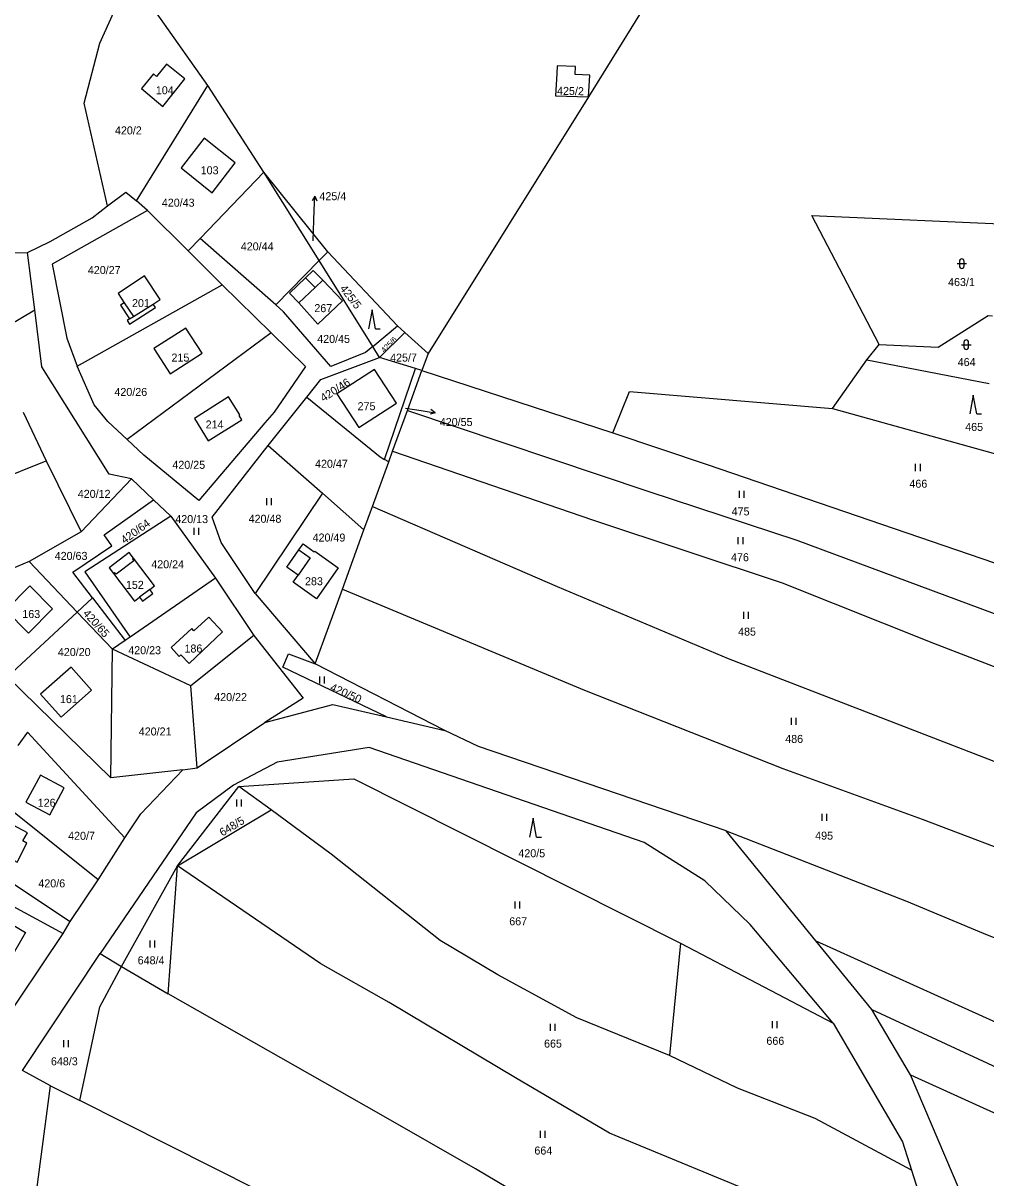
# Model space of a CAD drawing. Extents: x -7483133 to -743907, y -11317770 to -1129777.
# Drawn here: x -748843.6 to -748639.1, y -1130642.1 to -1130396.9 of the extents above; entities that cross this region are included whole.
import ezdxf

# ---------------------------------------------------------------- set-up
doc = ezdxf.new("R2010")
doc.units = 0
for name, color, linetype in [('Hranice parcel', 7, 'Continuous'), ('Parcelní čísla', 7, 'Continuous'), ('Pop  PČ popisy', 7, 'Continuous'), ('Vnitřní kresba', 7, 'Continuous'), ('Značky kultur', 7, 'Continuous')]:
    doc.layers.add(name, color=color, linetype=linetype)

msp = doc.modelspace()

# ---------------------------------------------------------------- linework, layer by layer
at = {"layer": 'Hranice parcel'}
for p, q in [((-748819.51, -1130434.58), (-748804.37, -1130410.14)), ((-748792.44, -1130428.53), (-748804.37, -1130410.14)), ((-748805.98, -1130442.59), (-748792.44, -1130428.53)), ((-748778.89, -1130445.44), (-748792.44, -1130428.53)), ((-748780.72, -1130447.3), (-748792.44, -1130428.53)), ((-748817.21, -1130436.65), (-748819.51, -1130434.58)), ((-748808.51, -1130445.24), (-748817.21, -1130436.65)), ((-748805.98, -1130442.59), (-748808.51, -1130445.24)), ((-748789.95, -1130456.7), (-748805.98, -1130442.59)), ((-748848.41, -1130445.73), (-748842.67, -1130445.58)), ((-748841.12, -1130457.78), (-748842.67, -1130445.58)), ((-748801.29, -1130452.44), (-748808.51, -1130445.24)), ((-748780.72, -1130447.3), (-748778.89, -1130445.44)), ((-748764.11, -1130461.14), (-748778.89, -1130445.44)), ((-748789.95, -1130456.7), (-748780.72, -1130447.3)), ((-748769.34, -1130465.53), (-748780.72, -1130447.3)), ((-748832.08, -1130469.75), (-748801.29, -1130452.44)), ((-748801.29, -1130452.44), (-748790.91, -1130462.62)), ((-748846.67, -1130461.06), (-748841.12, -1130457.78)), ((-748839.58, -1130469.86), (-748841.12, -1130457.78)), ((-748788.31, -1130458.17), (-748789.95, -1130456.7)), ((-748790.91, -1130462.62), (-748821.52, -1130485.28)), ((-748790.91, -1130462.62), (-748783.62, -1130469.82)), ((-748769.34, -1130465.53), (-748764.11, -1130461.14)), ((-748767.88, -1130467.87), (-748762.56, -1130462.59)), ((-748762.56, -1130462.59), (-748764.11, -1130461.14)), ((-748757.6, -1130467.05), (-748762.56, -1130462.59)), ((-748664.43, -1130468.41), (-748661.8, -1130465.15)), ((-748769.34, -1130465.53), (-748770.9, -1130466.83)), ((-748767.88, -1130467.87), (-748769.34, -1130465.53)), ((-748760.27, -1130470.2), (-748767.88, -1130467.87)), ((-748757.6, -1130467.05), (-748758.89, -1130470.62)), ((-748766.84, -1130489.51), (-748760.27, -1130470.2)), ((-748758.89, -1130470.62), (-748760.27, -1130470.2)), ((-748671.7, -1130478.68), (-748664.43, -1130468.41)), ((-748664.43, -1130468.41), (-748638.43, -1130473.4)), ((-748761.98, -1130479.13), (-748758.89, -1130470.62)), ((-748758.89, -1130470.62), (-748718.34, -1130483.88)), ((-748791.56, -1130486.57), (-748783.35, -1130476.32)), ((-748843.6, -1130479.46), (-748838.72, -1130489.81)), ((-748765.12, -1130487.78), (-748761.98, -1130479.13)), ((-748797.15, -1130481.13), (-748797.74, -1130480.18)), ((-748803.45, -1130501.81), (-748791.56, -1130486.57)), ((-748791.56, -1130486.57), (-748779.98, -1130496.71)), ((-748838.72, -1130489.81), (-748831.25, -1130504.91)), ((-748765.94, -1130490.05), (-748766.84, -1130489.51)), ((-748765.94, -1130490.05), (-748765.12, -1130487.78)), ((-748769.41, -1130499.53), (-748765.94, -1130490.05)), ((-748831.25, -1130504.91), (-748820.54, -1130493.62)), ((-748820.54, -1130493.62), (-748815.91, -1130498.09)), ((-748779.98, -1130496.71), (-748794.31, -1130518)), ((-748771.22, -1130504.47), (-748779.98, -1130496.71)), ((-748815.91, -1130498.09), (-748812.25, -1130501.61)), ((-748771.22, -1130504.47), (-748769.41, -1130499.53)), ((-748812.25, -1130501.61), (-748802.76, -1130514.74)), ((-748775.79, -1130517.06), (-748771.22, -1130504.47)), ((-748831.25, -1130504.91), (-748842.3, -1130511.21)), ((-748842.3, -1130511.21), (-748863.15, -1130519.89)), ((-748832.1, -1130521.99), (-748842.3, -1130511.21)), ((-748802.76, -1130514.74), (-748820.87, -1130527.26)), ((-748802.76, -1130514.74), (-748794.57, -1130526.92)), ((-748832.1, -1130521.99), (-748828.83, -1130518.95)), ((-748828.83, -1130518.95), (-748821.95, -1130528)), ((-748794.31, -1130518), (-748781.55, -1130532.95)), ((-748781.55, -1130532.95), (-748775.79, -1130517.06)), ((-748846.93, -1130535.69), (-748832.1, -1130521.99)), ((-748824.58, -1130529.82), (-748832.1, -1130521.99)), ((-748821.95, -1130528), (-748824.58, -1130529.82)), ((-748820.87, -1130527.26), (-748821.95, -1130528)), ((-748794.57, -1130526.92), (-748807.97, -1130537.59)), ((-748824.94, -1130557.15), (-748824.58, -1130529.82)), ((-748807.97, -1130537.59), (-748824.58, -1130529.82)), ((-748754, -1130547.08), (-748781.55, -1130532.95)), ((-748824.94, -1130557.15), (-748846.93, -1130535.69)), ((-748806.63, -1130555.06), (-748807.97, -1130537.59)), ((-748806.63, -1130555.06), (-748792.29, -1130545.43)), ((-748766.4, -1130544.2), (-748754, -1130547.08)), ((-748842.68, -1130547.42), (-748844.69, -1130550.29)), ((-748822.02, -1130569.92), (-748842.68, -1130547.42)), ((-748809.68, -1130555.47), (-748824.94, -1130557.15)), ((-748809.68, -1130555.47), (-748806.63, -1130555.06)), ((-748827.67, -1130578.81), (-748852.67, -1130558.78)), ((-748810.8, -1130575.84), (-748797.81, -1130558.97)), ((-748790.94, -1130563.97), (-748797.81, -1130558.97)), ((-748810.8, -1130575.84), (-748790.94, -1130563.97)), ((-748675.21, -1130591.78), (-748694.25, -1130568.39)), ((-748860.1, -1130570.08), (-748833.58, -1130587.64)), ((-748827.67, -1130578.81), (-748822.02, -1130569.92)), ((-748863.53, -1130574.84), (-748835.11, -1130590.22)), ((-748822.71, -1130597.23), (-748810.8, -1130575.84)), ((-748812.78, -1130603.03), (-748810.8, -1130575.84)), ((-748833.58, -1130587.64), (-748827.67, -1130578.81)), ((-748835.11, -1130590.22), (-748833.58, -1130587.64)), ((-748851.72, -1130614.96), (-748835.11, -1130590.22)), ((-748704.01, -1130592.27), (-748706.33, -1130616.12)), ((-748704.01, -1130592.27), (-748671.54, -1130609.27)), ((-748663.32, -1130606.39), (-748675.21, -1130591.78)), ((-748843.69, -1130619.33), (-748827.25, -1130594.48)), ((-748827.25, -1130594.48), (-748822.71, -1130597.23)), ((-748822.71, -1130597.23), (-748812.78, -1130603.03)), ((-748655.15, -1130620.24), (-748663.32, -1130606.39)), ((-748837.76, -1130622.58), (-748843.69, -1130619.33)), ((-748655.15, -1130620.24), (-748603.37, -1130643.75)), ((-748644.81, -1130644.52), (-748655.15, -1130620.24)), ((-748841.05, -1130647.3), (-748837.76, -1130622.58)), ((-748837.76, -1130622.58), (-748831.53, -1130625.71)), ((-748654.93, -1130640.47), (-748646.91, -1130665.97))]:
    msp.add_line(p, q, dxfattribs=at)
for points in [[(-748668.63, -1130323.88), (-748723.49, -1130412.55), (-748757.6, -1130467.05)], [(-748825.64, -1130435.7), (-748830.6, -1130413.85), (-748827.29, -1130401.09), (-748824.29, -1130394.55), (-748817.71, -1130391.16)], [(-748804.37, -1130410.14), (-748815.28, -1130394.69), (-748817.71, -1130391.16)], [(-748815.24, -1130408.18), (-748815.91, -1130407.67), (-748818.48, -1130410.72), (-748813.94, -1130414.55), (-748809.28, -1130408.69), (-748813.12, -1130405.56), (-748815.24, -1130408.18)], [(-748730.17, -1130405.92), (-748730.26, -1130407.59), (-748730.51, -1130412.32), (-748723.49, -1130412.55), (-748723.25, -1130407.92), (-748726.36, -1130407.78), (-748726.31, -1130406.11), (-748730.17, -1130405.92)], [(-748798.53, -1130426.57), (-748805.14, -1130421.28), (-748810.06, -1130427.6)], [(-748810.06, -1130427.6), (-748803.47, -1130432.9), (-748798.53, -1130426.57)], [(-748825.64, -1130435.7), (-748821.76, -1130432.75), (-748819.51, -1130434.58)], [(-748842.67, -1130445.58), (-748837.83, -1130443.26), (-748828.93, -1130438.2), (-748825.64, -1130435.7)], [(-748817.21, -1130436.65), (-748837.42, -1130448.09), (-748834.32, -1130463.8), (-748832.08, -1130469.75)], [(-748661.8, -1130465.15), (-748676.09, -1130437.74), (-748631.31, -1130439.73)], [(-748822.89, -1130456.78), (-748820.97, -1130459.7), (-748821.47, -1130460.02), (-748820.98, -1130460.78), (-748815.5, -1130457.27), (-748815.97, -1130456.53), (-748814.52, -1130455.58), (-748817.78, -1130450.55), (-748823.43, -1130454.26), (-748822.1, -1130456.26), (-748822.89, -1130456.78)], [(-748781, -1130460.83), (-748775.78, -1130455.82), (-748779.97, -1130451.47), (-748781.98, -1130449.37), (-748783.6, -1130450.93), (-748787.01, -1130454.2), (-748785.04, -1130456.25), (-748781, -1130460.83)], [(-748770.9, -1130466.83), (-748778.22, -1130469.78), (-748788.31, -1130458.17)], [(-748661.8, -1130465.15), (-748649.27, -1130465.67), (-748638.63, -1130458.96), (-748637.75, -1130459.01)], [(-748805.57, -1130466.96), (-748809.03, -1130461.64), (-748815.82, -1130465.97), (-748812.39, -1130471.35), (-748805.57, -1130466.96)], [(-748783.35, -1130476.32), (-748780.36, -1130472.52), (-748767.88, -1130467.87)], [(-748820.54, -1130493.62), (-748825.34, -1130492.64), (-748839.58, -1130469.86)], [(-748821.52, -1130485.28), (-748825.63, -1130481.5), (-748828.48, -1130477.93), (-748832.08, -1130469.75)], [(-748783.62, -1130469.82), (-748790.29, -1130479.46), (-748792.26, -1130481.76), (-748806.27, -1130498.24)], [(-748772.28, -1130482.78), (-748764.3, -1130477.55), (-748768.99, -1130470.4), (-748776.95, -1130475.63), (-748772.28, -1130482.78)], [(-748718.34, -1130483.88), (-748714.81, -1130475.07), (-748671.7, -1130478.68)], [(-748797.74, -1130480.18), (-748797.55, -1130480.06), (-748799.94, -1130476.26), (-748807.21, -1130480.86), (-748804.28, -1130485.57), (-748797.15, -1130481.13)], [(-748783.35, -1130476.32), (-748767.74, -1130488.96), (-748766.84, -1130489.51)], [(-748761.98, -1130479.13), (-748710.91, -1130496.25), (-748679.26, -1130506.7), (-748621.93, -1130527.97)], [(-748671.7, -1130478.68), (-748633.74, -1130489.24), (-748618.21, -1130483.5)], [(-748718.34, -1130483.88), (-748698.29, -1130490.59), (-748629.43, -1130514.15)], [(-748806.27, -1130498.24), (-748817.98, -1130488.65), (-748821.52, -1130485.28)], [(-748868.14, -1130501.65), (-748849.28, -1130494.06), (-748838.72, -1130489.81)], [(-748765.12, -1130487.78), (-748722.68, -1130502.34), (-748682.4, -1130515.73), (-748650.26, -1130528.57), (-748607.86, -1130544.88)], [(-748828.83, -1130518.95), (-748833.02, -1130513.48), (-748824.76, -1130507.89), (-748826.36, -1130505.51), (-748815.91, -1130498.09)], [(-748769.41, -1130499.53), (-748730.21, -1130516.5), (-748693.83, -1130531.8), (-748627.18, -1130557.56), (-748603.84, -1130566.17), (-748577.63, -1130576.56)], [(-748812.25, -1130501.61), (-748830.46, -1130513.37), (-748820.87, -1130527.26)], [(-748794.31, -1130518), (-748801.5, -1130507.17), (-748803.45, -1130501.81)], [(-748816.7, -1130517.18), (-748815.67, -1130516.4), (-748820.14, -1130510.48), (-748821.04, -1130509.29), (-748825.32, -1130512.52)], [(-748785.03, -1130508.74), (-748784.15, -1130507.49), (-748781.75, -1130509.19), (-748781.63, -1130509.04), (-748776.67, -1130512.52), (-748781.3, -1130519.11), (-748786.27, -1130515.61), (-748785.21, -1130514.11), (-748787.62, -1130512.4), (-748785.03, -1130508.74)], [(-748825.32, -1130512.52), (-748824.39, -1130513.73), (-748819.95, -1130519.63), (-748818.86, -1130518.81), (-748818.22, -1130519.65), (-748816.06, -1130518.02), (-748816.7, -1130517.18)], [(-748837.33, -1130521.27), (-748842.14, -1130516.36), (-748847.28, -1130521.51), (-748842.48, -1130526.4), (-748837.33, -1130521.27)], [(-748775.79, -1130517.06), (-748724.37, -1130538.57), (-748682.28, -1130555.19), (-748652.69, -1130565.92), (-748602.7, -1130584.94), (-748579.32, -1130593.13)], [(-748807.77, -1130525.47), (-748812.13, -1130529.47), (-748810.42, -1130531.37), (-748810.07, -1130531.04), (-748808.34, -1130532.87), (-748801.24, -1130526.14), (-748804.12, -1130523), (-748807.33, -1130525.95), (-748807.77, -1130525.47)], [(-748794.57, -1130526.92), (-748784.09, -1130540.23), (-748792.29, -1130545.43)], [(-748766.4, -1130544.2), (-748788.4, -1130533.64), (-748787.24, -1130530.81), (-748781.55, -1130532.95)], [(-748829.04, -1130538.57), (-748833.41, -1130533.62), (-748839.91, -1130539.35), (-748835.51, -1130544.26), (-748829.04, -1130538.57)], [(-748792.29, -1130545.43), (-748777.8, -1130541.55), (-748766.4, -1130544.2)], [(-748694.25, -1130568.39), (-748746.89, -1130550.49), (-748754, -1130547.08)], [(-748671.54, -1130609.27), (-748689.21, -1130588.28), (-748698.85, -1130579.03), (-748711.73, -1130570.87), (-748770.07, -1130550.7), (-748789.66, -1130553.8), (-748798.91, -1130558.69), (-748806.83, -1130564.57), (-748827.25, -1130594.48)], [(-748822.02, -1130569.92), (-748818.59, -1130564.8), (-748809.68, -1130555.47)], [(-748843.04, -1130562.3), (-748837.93, -1130565), (-748834.89, -1130559.25), (-748839.93, -1130556.59), (-748843.04, -1130562.3)], [(-748797.81, -1130558.97), (-748773.36, -1130557.37), (-748704.01, -1130592.27)], [(-748706.33, -1130616.12), (-748726.03, -1130608.16), (-748742.79, -1130598.99), (-748754.99, -1130591.71), (-748778.14, -1130573.4), (-748790.94, -1130563.97)], [(-748849.84, -1130572.35), (-748844.85, -1130575.03), (-748842.78, -1130571.05), (-748843.62, -1130570.55), (-748842.67, -1130568.81), (-748846.75, -1130566.64)], [(-748694.25, -1130568.39), (-748656.01, -1130583.36), (-748638.89, -1130590.49), (-748583.8, -1130611.89)], [(-748646.91, -1130665.97), (-748667.03, -1130655.85), (-748683.71, -1130647.2), (-748719.03, -1130632.64), (-748739.03, -1130620.84), (-748765.84, -1130604.86), (-748780.39, -1130596.64), (-748810.8, -1130575.84)], [(-748860.53, -1130579.57), (-748843.1, -1130589.97), (-748853.28, -1130607.58), (-748870.54, -1130596.92), (-748860.53, -1130579.57)], [(-748675.21, -1130591.78), (-748612.59, -1130620.06), (-748588.68, -1130630.55)], [(-748831.53, -1130625.71), (-748827.27, -1130605.82), (-748822.71, -1130597.23)], [(-748641.16, -1130692.96), (-748697.34, -1130665.81), (-748727.46, -1130652.12), (-748747.5, -1130640.2), (-748767.58, -1130628.74), (-748812.78, -1130603.03)], [(-748663.32, -1130606.39), (-748612.22, -1130630.04), (-748593.74, -1130637.98)], [(-748671.54, -1130609.27), (-748656.85, -1130634.49), (-748654.93, -1130640.47)], [(-748654.93, -1130640.47), (-748675.39, -1130629.49), (-748691.85, -1130623.03), (-748706.33, -1130616.12)], [(-748640.91, -1130717.3), (-748684.38, -1130697.1), (-748699.16, -1130689.78), (-748741.42, -1130670.29), (-748775.09, -1130654.15), (-748831.53, -1130625.71)]]:
    msp.add_lwpolyline(points, dxfattribs=at)
at = {"layer": 'Pop  PČ popisy'}
for p, q in [((-748781.66, -1130433.62), (-748782.19, -1130434.6)), ((-748781.76, -1130436.62), (-748781.66, -1130433.62)), ((-748781.66, -1130433.62), (-748781.19, -1130434.64)), ((-748781.98, -1130443.1), (-748781.76, -1130436.62)), ((-748762.38, -1130478.64), (-748759.07, -1130479.14)), ((-748759.07, -1130479.14), (-748756.11, -1130479.61)), ((-748756.11, -1130479.61), (-748757.17, -1130479.95)), ((-748756.11, -1130479.61), (-748757.02, -1130478.96))]:
    msp.add_line(p, q, dxfattribs=at)
at = {"layer": 'Vnitřní kresba'}
for p, q in [((-748781.59, -1130453.02), (-748785.04, -1130456.25)), ((-748783.6, -1130450.93), (-748781.59, -1130453.02)), ((-748781.59, -1130453.02), (-748779.97, -1130451.47)), ((-748822.1, -1130456.26), (-748820.16, -1130459.19)), ((-748820.16, -1130459.19), (-748815.97, -1130456.53)), ((-748820.97, -1130459.7), (-748820.16, -1130459.19)), ((-748785.03, -1130508.74), (-748782.61, -1130510.45)), ((-748820.09, -1130511.05), (-748823.86, -1130513.93)), ((-748820.14, -1130510.48), (-748820.38, -1130510.66)), ((-748820.38, -1130510.66), (-748820.09, -1130511.05)), ((-748782.61, -1130510.45), (-748785.21, -1130514.11)), ((-748824.15, -1130513.55), (-748824.39, -1130513.73)), ((-748823.86, -1130513.93), (-748824.15, -1130513.55)), ((-748816.7, -1130517.18), (-748818.86, -1130518.81))]:
    msp.add_line(p, q, dxfattribs=at)
at = {"layer": 'Značky kultur'}
for p, q in [((-748645.25, -1130447.95), (-748643.25, -1130447.95)), ((-748644.75, -1130447.45), (-748644.75, -1130448.45)), ((-748643.75, -1130448.45), (-748643.75, -1130447.45)), ((-748769.49, -1130457.79), (-748770.24, -1130461.79)), ((-748768.74, -1130461.79), (-748769.49, -1130457.79)), ((-748768.74, -1130461.79), (-748767.74, -1130461.79)), ((-748644.29, -1130465.16), (-748642.29, -1130465.16)), ((-748643.79, -1130464.66), (-748643.79, -1130465.66)), ((-748642.79, -1130465.66), (-748642.79, -1130464.66)), ((-748641.81, -1130475.88), (-748642.56, -1130479.88)), ((-748641.06, -1130479.88), (-748641.81, -1130475.88)), ((-748641.06, -1130479.88), (-748640.06, -1130479.88)), ((-748654.05, -1130491.99), (-748654.05, -1130490.49)), ((-748653.05, -1130491.99), (-748653.05, -1130490.49)), ((-748691.45, -1130497.67), (-748691.45, -1130496.17)), ((-748690.45, -1130497.67), (-748690.45, -1130496.17)), ((-748791.81, -1130499.23), (-748791.81, -1130497.73)), ((-748790.81, -1130499.23), (-748790.81, -1130497.73)), ((-748807.29, -1130505.55), (-748807.29, -1130504.05)), ((-748806.29, -1130505.55), (-748806.29, -1130504.05)), ((-748691.71, -1130507.54), (-748691.71, -1130506.04)), ((-748690.71, -1130507.54), (-748690.71, -1130506.04)), ((-748690.52, -1130523.4), (-748690.52, -1130521.9)), ((-748689.52, -1130523.4), (-748689.52, -1130521.9)), ((-748780.56, -1130537.12), (-748780.56, -1130535.62)), ((-748779.56, -1130537.12), (-748779.56, -1130535.62)), ((-748680.4, -1130545.89), (-748680.4, -1130544.39)), ((-748679.4, -1130545.89), (-748679.4, -1130544.39)), ((-748798.21, -1130563.27), (-748798.21, -1130561.77)), ((-748797.21, -1130563.27), (-748797.21, -1130561.77)), ((-748735.28, -1130565.73), (-748736.03, -1130569.73)), ((-748734.53, -1130569.73), (-748735.28, -1130565.73)), ((-748673.88, -1130566.3), (-748673.88, -1130564.8)), ((-748672.88, -1130566.3), (-748672.88, -1130564.8)), ((-748734.53, -1130569.73), (-748733.53, -1130569.73)), ((-748739.07, -1130584.92), (-748739.07, -1130583.42)), ((-748738.07, -1130584.92), (-748738.07, -1130583.42)), ((-748816.62, -1130593.21), (-748816.62, -1130591.71)), ((-748815.62, -1130593.21), (-748815.62, -1130591.71)), ((-748731.6, -1130610.9), (-748731.6, -1130609.4)), ((-748730.6, -1130610.9), (-748730.6, -1130609.4)), ((-748684.42, -1130610.31), (-748684.42, -1130608.81)), ((-748683.42, -1130610.31), (-748683.42, -1130608.81)), ((-748834.96, -1130614.36), (-748834.96, -1130612.86)), ((-748833.96, -1130614.36), (-748833.96, -1130612.86)), ((-748733.69, -1130633.61), (-748733.69, -1130632.11)), ((-748732.69, -1130633.61), (-748732.69, -1130632.11))]:
    msp.add_line(p, q, dxfattribs=at)
for centre, start, end in [((-748644.25, -1130447.45), 0, 180), ((-748644.25, -1130448.45), 180, 359.9879), ((-748643.29, -1130464.66), 0, 180), ((-748643.29, -1130465.66), 180, 359.9879)]:
    msp.add_arc(centre, 0.5, start, end, dxfattribs=at)

# ---------------------------------------------------------------- texts
at = {"layer": 'Parcelní čísla'}
for s, p in [('104', (-748815.4, -1130411.97)), ('420/2', (-748824.08, -1130420.5)), ('103', (-748805.88, -1130428.97)), ('425/4', (-748780.66, -1130434.47)), ('420/43', (-748814.13, -1130435.85)), ('420/44', (-748797.36, -1130445.13)), ('420/27', (-748829.84, -1130450.16)), ('463/1', (-748647.16, -1130452.71)), ('201', (-748820.46, -1130457.17)), ('267', (-748781.74, -1130458.25)), ('420/45', (-748781.13, -1130464.79)), ('215', (-748812.08, -1130468.75)), ('425/7', (-748765.65, -1130468.76)), ('464', (-748645.12, -1130469.71)), ('420/26', (-748824.2, -1130476.05)), ('275', (-748772.56, -1130479.08)), ('214', (-748804.83, -1130482.96)), ('420/55', (-748755.1, -1130482.43)), ('465', (-748643.52, -1130483.48)), ('420/25', (-748811.89, -1130491.52)), ('420/47', (-748781.59, -1130491.3)), ('466', (-748655.37, -1130495.54)), ('420/12', (-748831.98, -1130497.69)), ('475', (-748693.13, -1130501.42)), ('420/13', (-748811.27, -1130503.05)), ('420/48', (-748795.7, -1130502.98)), ('420/49', (-748782.11, -1130506.97)), ('420/63', (-748836.88, -1130510.87)), ('476', (-748693.25, -1130511.15)), ('420/24', (-748816.37, -1130512.65)), ('152', (-748821.76, -1130517.02)), ('283', (-748783.72, -1130516.25)), ('163', (-748843.76, -1130523.21)), ('485', (-748691.75, -1130526.95)), ('420/23', (-748821.26, -1130530.9)), ('186', (-748809.32, -1130530.54)), ('420/20', (-748836.21, -1130531.29)), ('161', (-748835.77, -1130541.29)), ('420/22', (-748803, -1130540.85)), ('420/21', (-748819.03, -1130548.16)), ('486', (-748681.74, -1130549.74)), ('126', (-748840.49, -1130563.29)), ('420/7', (-748834.03, -1130570.31)), ('495', (-748675.38, -1130570.28)), ('420/5', (-748738.41, -1130574.02)), ('420/6', (-748840.35, -1130580.42)), ('667', (-748740.35, -1130588.47)), ('648/4', (-748819.26, -1130596.76)), ('666', (-748685.74, -1130613.86)), ('665', (-748732.96, -1130614.45)), ('648/3', (-748837.68, -1130618.21)), ('664', (-748735.01, -1130637.16))]:
    msp.add_text(s, height=1.7, dxfattribs=at).set_placement(p)
for s, height, rotation, p in [('425/2', 1.7, 359, (-748730.21, -1130412.08)), ('425/5', 1.7, 308, (-748776.44, -1130453.27)), ('425/6', 1.14, 45, (-748766.9, -1130466.94)), ('420/46', 1.7, 33, (-748779.77, -1130477.36)), ('420/64', 1.7, 36, (-748822.05, -1130507.55)), ('420/65', 1.7, 312, (-748831, -1130522.33)), ('420/50', 1.7, 336, (-748778.55, -1130538.53)), ('648/5', 1.7, 31, (-748801.26, -1130569.64))]:
    msp.add_text(s, height=height, rotation=rotation, dxfattribs=at).set_placement(p)

doc.saveas('drawing.dxf')
